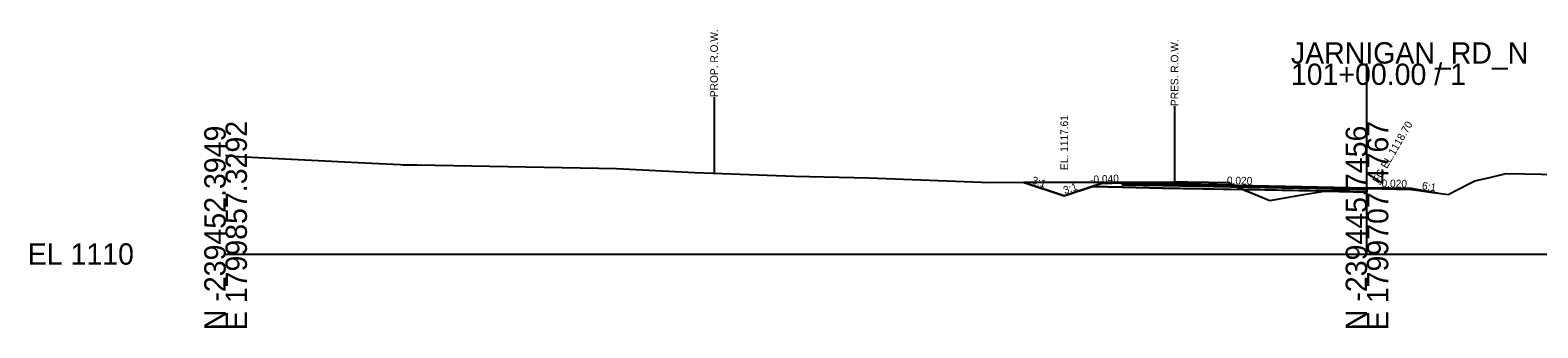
# Model space of a CAD drawing. Extents: x 214513 to 217151, y 214739 to 216780.
# Drawn here: x 215422.7 to 215620.8, y 214738.7 to 214777.7 of the extents above; entities that cross this region are included whole.
import ezdxf

# ---------------------------------------------------------------- set-up
doc = ezdxf.new("R2010")
doc.units = 0
for name, color, linetype in [('CONCEPT - TRANSPORTATION - Roads Text', 7, 'Continuous'), ('DESIGN - CENTERLINE - Proposed', 7, 'Continuous'), ('DESIGN - CENTERLINE - Proposed Text', 7, 'Continuous'), ('DESIGN - DRAINAGE - Special Ditches', 7, 'Continuous'), ('DESIGN - EARTHWORK - Shapes', 7, 'Continuous'), ('DESIGN - ROW - Right-of-Way Linework', 7, 'Continuous'), ('DESIGN - TRANSPORTATION - Text', 7, 'Continuous'), ('DESIGN - TYPICAL - Slope Tie Text', 7, 'Continuous'), ('Section', 7, 'Continuous'), ('SURVEY - DTM GRAPHICS - Triangles', 7, 'Continuous'), ('SURVEY - PROPERTY - ROW Lines', 7, 'Continuous'), ('XSCell', 7, 'Continuous')]:
    doc.layers.add(name, color=color, linetype=linetype)

msp = doc.modelspace()

# ---------------------------------------------------------------- linework, layer by layer
at = {"layer": 'DESIGN - DRAINAGE - Special Ditches'}
for points in [[(215558.57, 214755.98), (215553.28, 214757.74)], [(215563.43, 214757.6), (215558.57, 214755.98)], [(215566.24, 214757.71), (215566.24, 214757.46), (215571.53, 214757.35), (215598.36, 214756.81), (215598.36, 214756.48), (215571.53, 214757.02), (215566.24, 214757.13), (215562.27, 214757.21), (215563.43, 214757.6), (215566.24, 214757.71)], [(215566.24, 214757.71), (215598.36, 214757.06), (215598.36, 214756.96), (215598.36, 214756.96), (215566.24, 214757.61), (215566.24, 214757.61), (215566.24, 214757.71), (215566.24, 214757.71), (215566.24, 214757.71)], [(215566.24, 214757.61), (215598.36, 214756.96), (215598.36, 214756.81), (215598.36, 214756.81), (215566.24, 214757.46), (215566.24, 214757.46), (215566.24, 214757.61), (215566.24, 214757.61), (215566.24, 214757.61)], [(215604.19, 214756.95), (215598.36, 214757.06), (215598.36, 214756.96), (215598.36, 214756.96), (215604.19, 214756.85), (215604.19, 214756.85), (215604.19, 214756.85), (215604.19, 214756.95), (215604.19, 214756.95)], [(215604.19, 214756.95), (215607.64, 214756.37)]]:
    msp.add_lwpolyline(points, dxfattribs=at)
at = {"layer": 'DESIGN - EARTHWORK - Shapes'}
for p, q in [((215553.28, 214757.74), (215558.57, 214755.98)), ((215563.43, 214757.6), (215566.24, 214757.71)), ((215566.24, 214757.71), (215580.73, 214757.42)), ((215566.24, 214757.61), (215566.24, 214757.71)), ((215566.24, 214757.71), (215566.24, 214757.61)), ((215580.73, 214757.42), (215566.24, 214757.71)), ((215566.24, 214757.46), (215566.24, 214757.61)), ((215566.24, 214757.61), (215566.24, 214757.46)), ((215580.92, 214757.31), (215566.24, 214757.61)), ((215566.24, 214757.61), (215580.92, 214757.31)), ((215571.53, 214757.35), (215566.24, 214757.46)), ((215566.24, 214757.46), (215571.53, 214757.35)), ((215581.25, 214757.16), (215571.53, 214757.35)), ((215571.53, 214757.35), (215581.25, 214757.16)), ((215580.92, 214757.31), (215580.73, 214757.42)), ((215582.11, 214756.81), (215581.25, 214757.16)), ((215592.97, 214756.59), (215582.11, 214756.81)), ((215596.84, 214756.85), (215592.97, 214756.59)), ((215592.97, 214756.59), (215598.36, 214756.48)), ((215598.36, 214756.94), (215596.84, 214756.85)), ((215598.36, 214756.81), (215596.84, 214756.85)), ((215596.84, 214756.85), (215598.36, 214756.81)), ((215598.36, 214756.96), (215598.36, 214756.94)), ((215598.36, 214756.94), (215598.61, 214756.96)), ((215598.61, 214756.96), (215598.36, 214756.96)), ((215598.36, 214756.81), (215598.36, 214756.94)), ((215598.36, 214756.48), (215598.36, 214756.81)), ((215598.61, 214756.96), (215602.73, 214756.88)), ((215607.64, 214756.37), (215604.19, 214756.95))]:
    msp.add_line(p, q, dxfattribs=at)
for points in [[(215580.73, 214757.42), (215580.23, 214757.69), (215574.83, 214757.78), (215574.74, 214757.78), (215574.16, 214757.79), (215573.45, 214757.78), (215573.07, 214757.78), (215553.28, 214757.74)], [(215558.57, 214755.98), (215562.27, 214757.21), (215563.43, 214757.6)], [(215566.24, 214757.71), (215563.43, 214757.6), (215562.27, 214757.21), (215566.24, 214757.13), (215571.53, 214757.02), (215582.11, 214756.81)], [(215581.25, 214757.16), (215581.07, 214757.23), (215580.92, 214757.31)], [(215582.11, 214756.81), (215585.58, 214755.4), (215590.04, 214756.16), (215592.23, 214756.54), (215592.49, 214756.56), (215592.97, 214756.59)], [(215602.73, 214756.88), (215598.67, 214756.96), (215598.61, 214756.96)], [(215604.19, 214756.95), (215604.19, 214756.85), (215602.73, 214756.88)], [(215602.73, 214756.88), (215604.11, 214756.85), (215604.19, 214756.85), (215604.24, 214756.84), (215607.64, 214756.37)]]:
    msp.add_lwpolyline(points, dxfattribs=at)
at = {"layer": 'DESIGN - ROW - Right-of-Way Linework'}
msp.add_lwpolyline([(215512.55, 214768.95), (215512.55, 214758.95)], dxfattribs=at)
at = {"layer": 'SURVEY - DTM GRAPHICS - Triangles'}
msp.add_lwpolyline([(215448.36, 214761.33), (215449.99, 214761.17), (215466.67, 214760.31), (215471.32, 214760.1), (215471.68, 214760.08), (215473.53, 214760.08), (215499.74, 214759.57), (215510.02, 214759.04), (215523.12, 214758.58), (215532.89, 214758.38), (215548.83, 214757.73), (215573.45, 214757.78), (215574.16, 214757.79), (215574.74, 214757.78), (215574.83, 214757.78), (215580.23, 214757.69), (215581.07, 214757.23), (215585.58, 214755.4), (215590.04, 214756.16), (215592.23, 214756.54), (215592.49, 214756.56), (215598.67, 214756.96), (215604.11, 214756.85), (215604.19, 214756.85), (215604.24, 214756.84), (215609.03, 214756.18), (215611.75, 214757.56), (215612.53, 214757.95), (215614.67, 214758.43), (215616.67, 214758.91), (215619.04, 214758.89), (215628.01, 214758.73)], dxfattribs=at)
at = {"layer": 'SURVEY - PROPERTY - ROW Lines'}
msp.add_lwpolyline([(215573.07, 214767.78), (215573.07, 214757.78)], dxfattribs=at)
at = {"layer": 'XSCell'}
for p, q in [((215598.36, 214748.36), (215598.36, 214773.36)), ((215448.36, 214748.36), (215598.36, 214748.36)), ((215598.36, 214748.36), (215748.36, 214748.36))]:
    msp.add_line(p, q, dxfattribs=at)

# ---------------------------------------------------------------- texts
at = {"layer": 'CONCEPT - TRANSPORTATION - Roads Text'}
for s, rotation, p in [('-0.040', 2.2906, (215561.98, 214757.64)), ('0.020', 358.8542, (215579.94, 214757.53)), ('-0.020', 358.8542, (215599.82, 214757.16))]:
    msp.add_text(s, height=1, rotation=rotation, dxfattribs=at).set_placement(p)
at = {"layer": 'DESIGN - CENTERLINE - Proposed'}
msp.add_text('EL. 1117.61', height=1, rotation=90, dxfattribs=at).set_placement((215559.07, 214759.38))
at = {"layer": 'DESIGN - CENTERLINE - Proposed Text'}
msp.add_text('FG EL.1118.70', height=1, rotation=60, dxfattribs=at).set_placement((215599.86, 214757.56))
at = {"layer": 'DESIGN - TRANSPORTATION - Text'}
for s, p in [('PROP. R.O.W.', (215513.05, 214768.95)), ('PRES. R.O.W.', (215573.57, 214767.78))]:
    msp.add_text(s, height=1, rotation=90, dxfattribs=at).set_placement(p)
at = {"layer": 'DESIGN - TYPICAL - Slope Tie Text'}
for s, rotation, p in [('3:1', 341.5651, (215554.22, 214757.64)), ('3:1', 18.4349, (215558.64, 214756.22)), ('6:1', 350.5377, (215605.53, 214756.88))]:
    msp.add_text(s, height=1, rotation=rotation, dxfattribs=at).set_placement(p)
at = {"layer": 'Section'}
msp.add_text('-', height=0.0001, dxfattribs=at).set_placement((215448.36, 214748.36))
at = {"layer": 'XSCell'}
for s, p in [('JARNIGAN_RD_N', (215588.36, 214773.36)), ('101+00.00 / 1', (215588.36, 214770.56)), ('EL 1110', (215422.36, 214746.96))]:
    msp.add_text(s, height=2.8, dxfattribs=at).set_placement(p)
for s, p in [('N -239452.3949', (215448.36, 214738.36)), ('E 1799857.3292', (215451.16, 214738.36)), ('N -239445.7456', (215598.36, 214738.36)), ('E 1799707.4767', (215601.16, 214738.36))]:
    msp.add_text(s, height=2.8, rotation=90, dxfattribs=at).set_placement(p)

doc.saveas('drawing.dxf')
